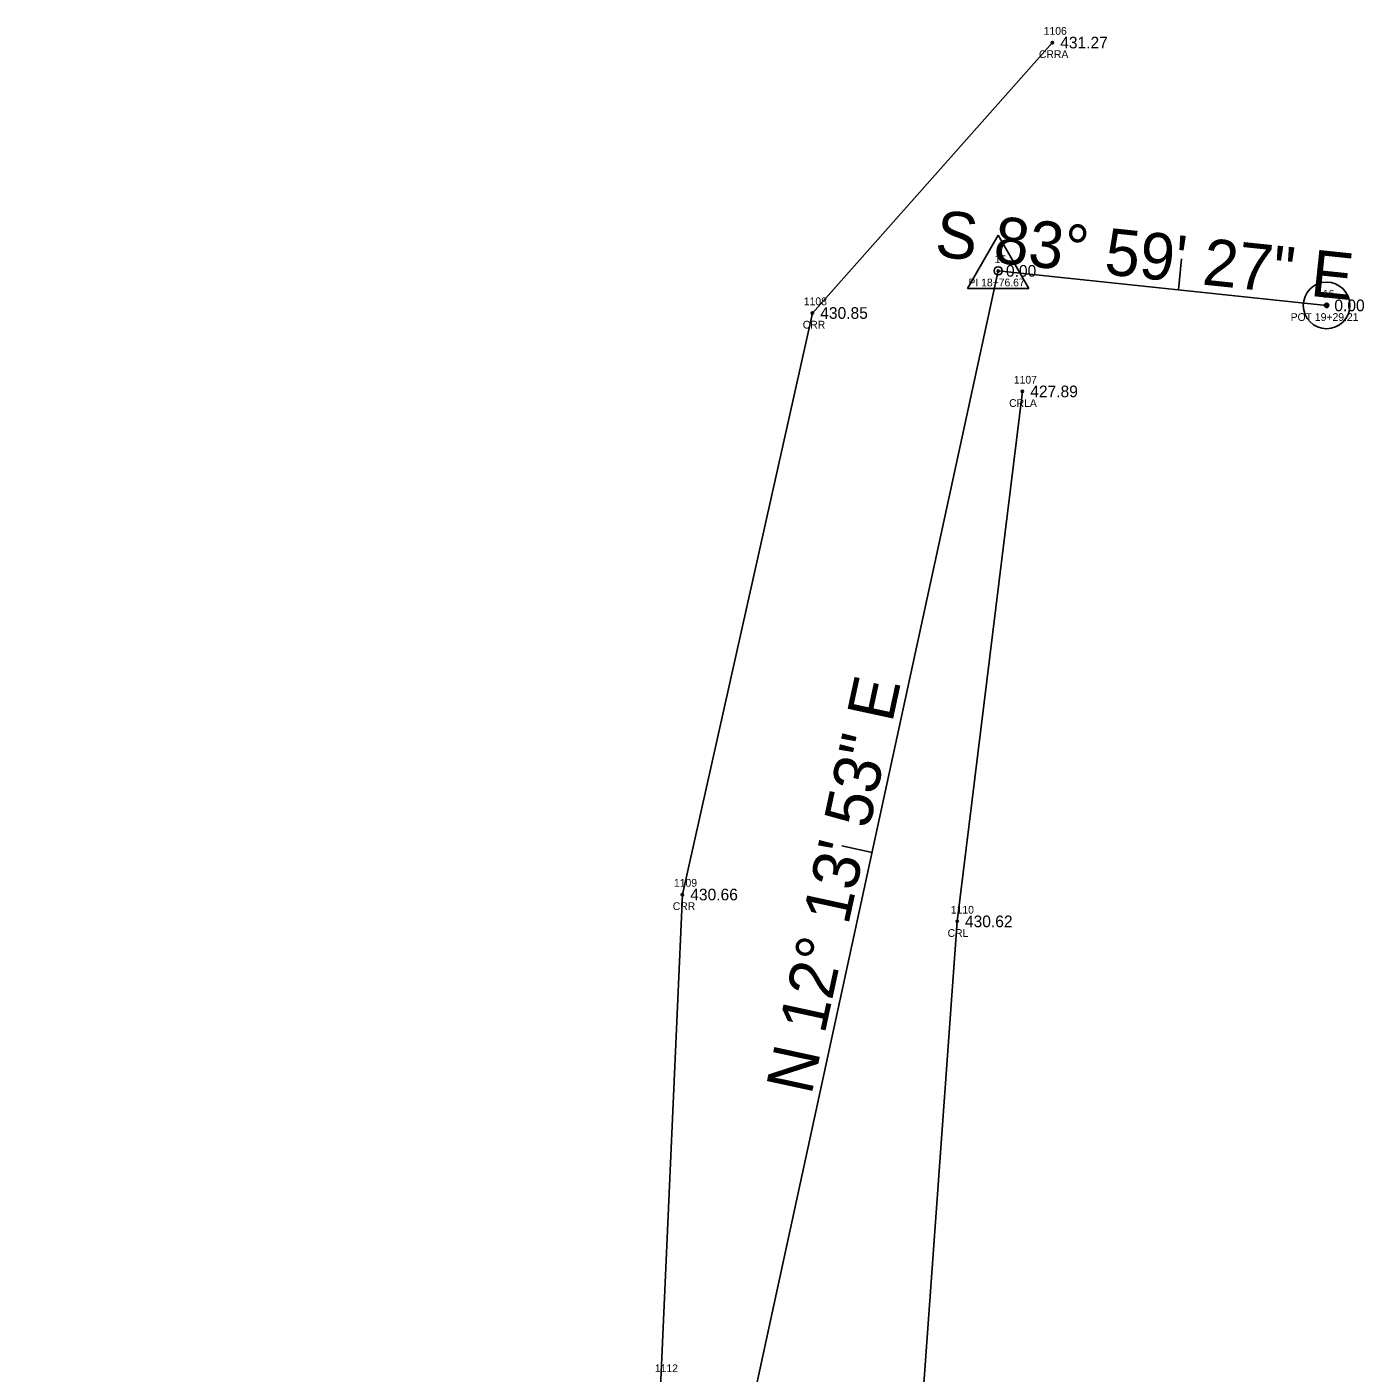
# Model space of a CAD drawing. Extents: x 1858454 to 1858924, y 1147053 to 1148170.
# Drawn here: x 1858751.6 to 1858923.8, y 1147976.1 to 1148149.5 of the extents above; entities that cross this region are included whole.
import ezdxf

# ---------------------------------------------------------------- set-up
doc = ezdxf.new("R2010")
doc.units = 0
for name, color, linetype in [('RD_EX_H2O', 7, 'Continuous'), ('RD_EX_H2O_txCode', 7, 'Continuous'), ('RD_EX_TX_H2O_ELEV', 7, 'Continuous'), ('RD_HC_Cl', 7, 'Continuous'), ('RD_HC_Data', 7, 'Continuous'), ('RD_HC_Data_Tic', 7, 'Continuous'), ('RD_HC_Survey_ELEV', 7, 'Continuous'), ('RD_HC_txCode', 7, 'Continuous'), ('RD_SMD_Locator', 7, 'Continuous')]:
    doc.layers.add(name, color=color, linetype=linetype)

msp = doc.modelspace()

# ---------------------------------------------------------------- linework, layer by layer
at = {"layer": 'RD_EX_H2O'}
for points in [[(1858883.69, 1148147.48), (1858852.78, 1148112.64), (1858836.04, 1148037.73), (1858833.26, 1147975.2), (1858828.33, 1147910.84), (1858842, 1147848.22), (1858847.52, 1147794.04)], [(1858879.83, 1148102.54), (1858871.42, 1148034.27), (1858866.93, 1147971.73), (1858863.21, 1147909.44), (1858860.9, 1147860.04), (1858873.82, 1147825.54), (1858891.79, 1147781.55), (1858894.95, 1147773.07), (1858887.01, 1147735.25), (1858825.08, 1147733.03), (1858791.14, 1147702.41), (1858765.02, 1147654.77), (1858740.99, 1147628.76), (1858706.35, 1147596.83), (1858671.87, 1147580.02), (1858637.61, 1147560.56), (1858613.46, 1147539.88), (1858609.2, 1147499), (1858608.26, 1147474.71), (1858583.43, 1147442.99), (1858542.68, 1147417.32), (1858497.34, 1147430.55)]]:
    msp.add_lwpolyline(points, dxfattribs=at)
at = {"layer": 'RD_HC_Cl'}
for p, q in [((1858842.19, 1147958.88), (1858876.7, 1148118.07)), ((1858876.7, 1148118.07), (1858919, 1148113.62))]:
    msp.add_line(p, q, dxfattribs=at)
at = {"layer": 'RD_HC_Data'}
for p, q in [((1858872.73, 1148115.78), (1858876.7, 1148122.66)), ((1858876.7, 1148122.66), (1858880.67, 1148115.78)), ((1858872.73, 1148115.78), (1858880.67, 1148115.78))]:
    msp.add_line(p, q, dxfattribs=at)
for centre, radius in [((1858876.7, 1148118.07), 0.529), ((1858919, 1148113.62), 3), ((1858919, 1148113.62), 0.282)]:
    msp.add_circle(centre, radius, dxfattribs=at)
at = {"layer": 'RD_HC_Data_Tic'}
for p, q in [((1858899.91, 1148115.63), (1858900.33, 1148119.61)), ((1858860.46, 1148043.15), (1858856.55, 1148044))]:
    msp.add_line(p, q, dxfattribs=at)
at = {"layer": 'RD_SMD_Locator'}
for centre in [(1858883.69, 1148147.48), (1858876.7, 1148118.07), (1858919, 1148113.62), (1858852.78, 1148112.64), (1858879.83, 1148102.54), (1858836.04, 1148037.73), (1858871.42, 1148034.27)]:
    msp.add_circle(centre, 0.15, dxfattribs=at)

# ---------------------------------------------------------------- texts
at = {"layer": 'RD_EX_H2O_txCode'}
for s, p in [('1106', (1858882.56, 1148148.48)), ('CRRA', (1858881.95, 1148145.48)), ('1108', (1858851.67, 1148113.64)), ('CRR', (1858851.53, 1148110.64)), ('1107', (1858878.72, 1148103.54)), ('CRLA', (1858878.11, 1148100.54)), ('1109', (1858834.94, 1148038.73)), ('CRR', (1858834.79, 1148035.73)), ('1110', (1858870.6, 1148035.27)), ('CRL', (1858870.19, 1148032.27)), ('1112', (1858832.48, 1147976.2))]:
    msp.add_text(s, height=1, dxfattribs=at).set_placement(p)
at = {"layer": 'RD_EX_TX_H2O_ELEV'}
for s, p in [('431.27', (1858884.69, 1148146.73)), ('430.85', (1858853.78, 1148111.89)), ('427.89', (1858880.83, 1148101.79)), ('430.66', (1858837.04, 1148036.98)), ('430.62', (1858872.42, 1148033.52))]:
    msp.add_text(s, height=1.5, dxfattribs=at).set_placement(p)
at = {"layer": 'RD_HC_Data'}
for s, rotation, p in [('S 83%%d 59\' 27" E', 353.991, (1858868.42, 1148119.95)), ('N 12%%d 13\' 53" E', 77.7685, (1858852.64, 1148011.79))]:
    msp.add_text(s, height=6, rotation=rotation, dxfattribs=at).set_placement(p)
at = {"layer": 'RD_HC_Survey_ELEV'}
for p in [(1858877.7, 1148117.32), (1858920, 1148112.87)]:
    msp.add_text('0.00', height=1.5, dxfattribs=at).set_placement(p)
at = {"layer": 'RD_HC_txCode'}
for s, p in [('15', (1858876.25, 1148119.07)), ('PI 18+76.67', (1858872.87, 1148116.07)), ('16', (1858918.53, 1148114.62)), ('POT 19+29.21', (1858914.37, 1148111.62))]:
    msp.add_text(s, height=1, dxfattribs=at).set_placement(p)

doc.saveas('drawing.dxf')
